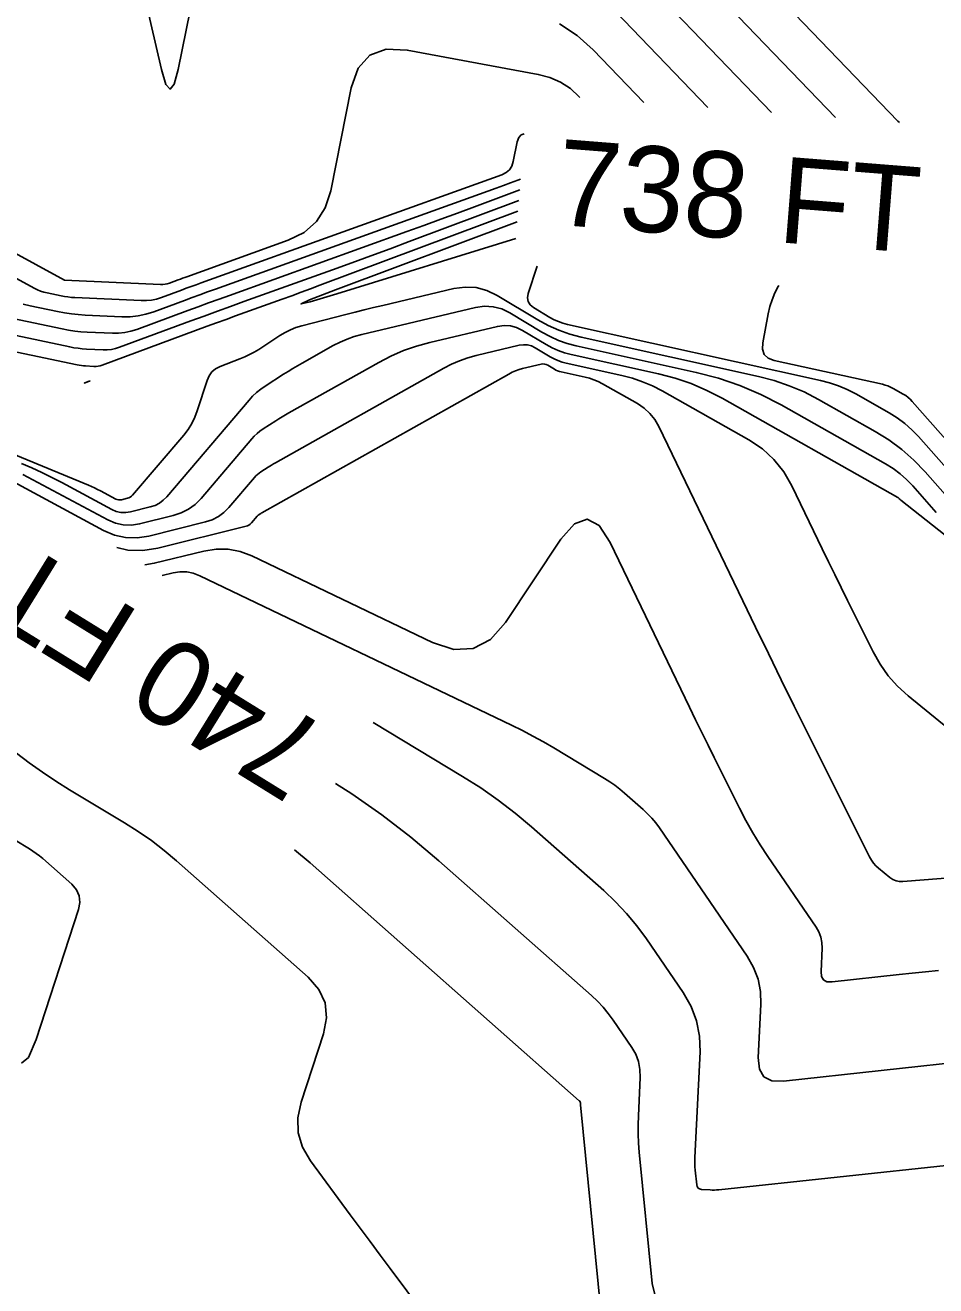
# Model space of a CAD drawing. Extents: x 1354696 to 1366163, y 660729 to 670380.
# Drawn here: x 1361169.7 to 1361233.4, y 664810.1 to 664898.2 of the extents above; entities that cross this region are included whole.
import ezdxf

# ---------------------------------------------------------------- set-up
doc = ezdxf.new("R2010")
doc.units = 0
doc.layers.add('R_Contour Annot', color=7, linetype='Continuous')
doc.layers.add('R_Contours', color=7, linetype='Continuous')

msp = doc.modelspace()

# ---------------------------------------------------------------- linework, layer by layer
at = {"layer": 'R_Contours'}
for points in [[(1361230.827, 664891.392), (1361230.814, 664891.4), (1361230.712, 664891.488), (1361207.938, 664915.166), (1361207.657, 664915.418), (1361207.348, 664915.618), (1361207.011, 664915.766), (1361206.647, 664915.862), (1361205.133, 664916.144), (1361204.754, 664916.21), (1361204.373, 664916.266), (1361203.991, 664916.313), (1361203.608, 664916.351), (1361192.611, 664917.287), (1361190.73, 664917.615), (1361189.007, 664918.265), (1361187.444, 664919.238), (1361186.04, 664920.532), (1361180.454, 664926.67), (1361179.143, 664927.771), (1361177.736, 664928.302), (1361176.233, 664928.261), (1361174.634, 664927.648), (1361166.891, 664923.427)], [(1361169.633, 664915.652), (1361195.317, 664913.464), (1361196.533, 664913.346), (1361197.746, 664913.197), (1361198.955, 664913.018), (1361200.159, 664912.809), (1361204.969, 664911.913), (1361206.127, 664911.607), (1361207.196, 664911.136), (1361208.177, 664910.501), (1361209.069, 664909.702), (1361226.339, 664891.747)], [(1361151.88, 664906.534), (1361170.71, 664912.233), (1361170.948, 664912.287), (1361171.186, 664912.303), (1361171.423, 664912.283), (1361171.66, 664912.225), (1361172.607, 664911.919), (1361172.845, 664911.849), (1361173.086, 664911.794), (1361173.329, 664911.752), (1361173.576, 664911.724), (1361187.025, 664910.578), (1361189.075, 664910.378), (1361191.119, 664910.127), (1361193.155, 664909.826), (1361195.185, 664909.473), (1361203.29, 664907.964), (1361205.242, 664907.448), (1361207.044, 664906.655), (1361208.697, 664905.585), (1361210.2, 664904.238), (1361221.876, 664892.1)], [(1361163.516, 664905.861), (1361172.724, 664908.648), (1361173.122, 664908.738), (1361173.519, 664908.765), (1361173.916, 664908.73), (1361174.313, 664908.634), (1361175.897, 664908.122), (1361176.295, 664908.006), (1361176.698, 664907.912), (1361177.106, 664907.842), (1361177.518, 664907.795), (1361182.556, 664907.366), (1361183.532, 664907.271), (1361184.505, 664907.152), (1361185.474, 664907.008), (1361186.44, 664906.84), (1361202.968, 664903.762), (1361205.06, 664903.209), (1361206.992, 664902.359), (1361208.764, 664901.212), (1361210.376, 664899.768), (1361217.412, 664892.452)], [(1361181.508, 664900.634), (1361180.407, 664895.112), (1361180.127, 664894.075), (1361179.836, 664893.727), (1361179.537, 664894.067), (1361179.227, 664895.095), (1361177.01, 664904.769)], [(1361212.949, 664892.805), (1361209.408, 664896.486), (1361208.289, 664897.489), (1361207.059, 664898.285)], [(1361208.485, 664893.158), (1361208.44, 664893.205), (1361207.814, 664893.765), (1361207.127, 664894.21), (1361206.377, 664894.54), (1361205.565, 664894.755), (1361196.409, 664896.46), (1361194.942, 664896.523), (1361193.801, 664896.102), (1361192.987, 664895.2), (1361192.499, 664893.815), (1361191.065, 664886.622), (1361190.687, 664885.444), (1361190.065, 664884.476), (1361189.2, 664883.719), (1361188.091, 664883.171), (1361181.009, 664880.624), (1361180.857, 664880.569), (1361180.705, 664880.514), (1361180.553, 664880.458), (1361180.401, 664880.403), (1361179.794, 664880.178), (1361179.641, 664880.13), (1361179.485, 664880.098), (1361179.327, 664880.082), (1361179.167, 664880.081), (1361172.461, 664880.386), (1361172.454, 664880.387), (1361172.453, 664880.388), (1361160.148, 664887.1)], [(1361161.836, 664884.468), (1361170.34, 664879.829), (1361170.559, 664879.72), (1361170.783, 664879.627), (1361171.015, 664879.551), (1361171.252, 664879.492), (1361172.214, 664879.29), (1361172.455, 664879.245), (1361172.697, 664879.209), (1361172.941, 664879.183), (1361173.186, 664879.167), (1361177.819, 664878.957), (1361178.184, 664878.958), (1361178.543, 664878.995), (1361178.896, 664879.068), (1361179.244, 664879.178), (1361180.623, 664879.687), (1361180.968, 664879.814), (1361181.313, 664879.94), (1361181.659, 664880.065), (1361182.005, 664880.19), (1361203.028, 664887.751), (1361203.326, 664887.898), (1361203.558, 664888.101), (1361203.725, 664888.36), (1361203.826, 664888.676), (1361204.1, 664890.052), (1361204.203, 664890.345), (1361204.376, 664890.536), (1361204.58, 664890.611)], [(1361168.845, 664877.704), (1361172.304, 664876.977), (1361172.735, 664876.896), (1361173.169, 664876.832), (1361173.605, 664876.785), (1361174.044, 664876.757), (1361175.802, 664876.677), (1361176.238, 664876.678), (1361176.668, 664876.723), (1361177.091, 664876.811), (1361177.507, 664876.941), (1361181.067, 664878.255), (1361181.799, 664878.524), (1361182.531, 664878.792), (1361183.263, 664879.058), (1361183.996, 664879.322), (1361196.389, 664883.779), (1361197.573, 664884.207), (1361198.755, 664884.638), (1361199.936, 664885.073), (1361201.115, 664885.512), (1361204.271, 664886.691)], [(1361204.33, 664887.437), (1361204.138, 664887.366), (1361203.639, 664887.182), (1361203.139, 664886.999), (1361202.639, 664886.819), (1361183, 664879.756), (1361182.461, 664879.562), (1361181.922, 664879.366), (1361181.383, 664879.169), (1361180.845, 664878.971), (1361178.693, 664878.177), (1361178.151, 664878.007), (1361177.6, 664877.892), (1361177.04, 664877.834), (1361176.472, 664877.832), (1361173.91, 664877.948), (1361173.421, 664877.98), (1361172.935, 664878.032), (1361172.451, 664878.104), (1361171.969, 664878.195), (1361170.048, 664878.598), (1361169.574, 664878.716)], [(1361204.212, 664885.946), (1361196.548, 664883.082), (1361195.211, 664882.585), (1361193.872, 664882.092), (1361192.533, 664881.603), (1361191.191, 664881.118), (1361184.992, 664878.889), (1361184.065, 664878.554), (1361183.139, 664878.218), (1361182.214, 664877.88), (1361181.29, 664877.54), (1361176.295, 664875.697), (1361176.018, 664875.609), (1361175.736, 664875.551), (1361175.449, 664875.521), (1361175.159, 664875.52), (1361173.986, 664875.573), (1361173.694, 664875.593), (1361173.403, 664875.624), (1361173.113, 664875.666), (1361172.826, 664875.721), (1361166.52, 664877.046)], [(1361164.113, 664876.404), (1361173.347, 664874.464), (1361173.492, 664874.437), (1361173.636, 664874.415), (1361173.782, 664874.4), (1361173.928, 664874.39), (1361174.515, 664874.364), (1361174.661, 664874.364), (1361174.804, 664874.379), (1361174.945, 664874.408), (1361175.084, 664874.452), (1361182.438, 664877.166), (1361183.092, 664877.407), (1361183.747, 664877.646), (1361184.402, 664877.884), (1361185.058, 664878.12), (1361187.682, 664879.064), (1361188.337, 664879.301), (1361188.992, 664879.54), (1361189.646, 664879.781), (1361190.299, 664880.024), (1361204.153, 664885.201)], [(1361204.002, 664883.286), (1361191.487, 664879.423), (1361189.624, 664878.867), (1361188.987, 664878.73), (1361189.575, 664879.01), (1361191.39, 664879.708), (1361204.094, 664884.456)], [(1361239.418, 664861.244), (1361232.153, 664869.457), (1361231.692, 664869.937), (1361231.196, 664870.374), (1361230.665, 664870.768), (1361230.098, 664871.119), (1361227.765, 664872.436), (1361227.172, 664872.742), (1361226.562, 664873.003), (1361225.934, 664873.216), (1361225.289, 664873.384), (1361207.616, 664877.292), (1361207.294, 664877.377), (1361206.983, 664877.487), (1361206.681, 664877.622), (1361206.39, 664877.782), (1361205.243, 664878.472), (1361205.006, 664878.662), (1361204.865, 664878.89), (1361204.822, 664879.153), (1361204.876, 664879.453), (1361205.489, 664881.357)], [(1361235.92, 664863.244), (1361232.601, 664866.996), (1361231.818, 664867.811), (1361230.976, 664868.552), (1361230.075, 664869.221), (1361229.114, 664869.816), (1361225.154, 664872.052), (1361224.149, 664872.571), (1361223.114, 664873.013), (1361222.049, 664873.376), (1361220.954, 664873.66), (1361208.57, 664876.399), (1361207.774, 664876.608), (1361207.003, 664876.88), (1361206.257, 664877.214), (1361205.535, 664877.61), (1361202.699, 664879.318), (1361201.978, 664879.668), (1361201.232, 664879.863), (1361200.463, 664879.904), (1361199.669, 664879.791), (1361194.714, 664878.621), (1361194.062, 664878.466), (1361193.412, 664878.307), (1361192.762, 664878.145), (1361192.113, 664877.979), (1361189.034, 664877.186), (1361188.634, 664877.066), (1361188.249, 664876.915), (1361187.877, 664876.733), (1361187.518, 664876.519), (1361186.029, 664875.55), (1361185.715, 664875.357), (1361185.391, 664875.181), (1361185.059, 664875.023), (1361184.718, 664874.882), (1361183.337, 664874.352), (1361183.02, 664874.192), (1361182.762, 664873.977), (1361182.562, 664873.707), (1361182.419, 664873.383), (1361181.735, 664871.261), (1361181.562, 664870.801), (1361181.347, 664870.366), (1361181.089, 664869.954), (1361180.789, 664869.565), (1361177.206, 664865.363), (1361177.132, 664865.288), (1361177.049, 664865.227), (1361176.958, 664865.18), (1361176.857, 664865.147), (1361176.439, 664865.044), (1361176.336, 664865.027), (1361176.235, 664865.03), (1361176.137, 664865.052), (1361176.041, 664865.094), (1361174.982, 664865.661), (1361174.773, 664865.77), (1361174.561, 664865.874), (1361174.347, 664865.972), (1361174.13, 664866.064), (1361149.744, 664876.128)], [(1361222.378, 664880.022), (1361222.337, 664879.949), (1361222.109, 664879.491), (1361221.917, 664879.019), (1361221.763, 664878.534), (1361221.647, 664878.035), (1361221.257, 664876.013), (1361221.235, 664875.556), (1361221.363, 664875.199), (1361221.64, 664874.94), (1361222.068, 664874.779), (1361229.625, 664873.108), (1361229.82, 664873.057), (1361230.011, 664872.992), (1361230.195, 664872.914), (1361230.375, 664872.821), (1361231.083, 664872.421), (1361231.254, 664872.315), (1361231.415, 664872.196), (1361231.566, 664872.063), (1361231.705, 664871.917), (1361243.389, 664858.709)], [(1361169.453, 664867.567), (1361170.168, 664867.261), (1361170.876, 664866.937), (1361171.575, 664866.596), (1361172.265, 664866.237), (1361175.757, 664864.364), (1361176.074, 664864.228), (1361176.399, 664864.155), (1361176.732, 664864.145), (1361177.073, 664864.199), (1361178.453, 664864.54), (1361178.783, 664864.649), (1361179.085, 664864.803), (1361179.359, 664865.004), (1361179.603, 664865.252), (1361185.353, 664871.995), (1361185.608, 664872.274), (1361185.882, 664872.532), (1361186.174, 664872.769), (1361186.484, 664872.985), (1361187.761, 664873.808), (1361188.082, 664874.011), (1361188.406, 664874.209), (1361188.732, 664874.403), (1361189.062, 664874.591), (1361191.233, 664875.812), (1361191.713, 664876.06), (1361192.206, 664876.272), (1361192.712, 664876.45), (1361193.233, 664876.592), (1361201.194, 664878.472), (1361201.821, 664878.561), (1361202.428, 664878.528), (1361203.016, 664878.374), (1361203.586, 664878.098), (1361205.825, 664876.75), (1361206.395, 664876.437), (1361206.984, 664876.174), (1361207.593, 664875.959), (1361208.221, 664875.793), (1361216.618, 664873.937), (1361218.163, 664873.535), (1361219.665, 664873.023), (1361221.126, 664872.4), (1361222.544, 664871.667), (1361229.847, 664867.545), (1361230.369, 664867.221), (1361230.859, 664866.858), (1361231.317, 664866.454), (1361231.743, 664866.011), (1361233.382, 664864.158)], [(1361246.854, 664852.442), (1361230.912, 664865.009), (1361230.894, 664865.024), (1361230.877, 664865.039), (1361230.86, 664865.055), (1361230.845, 664865.072), (1361230.783, 664865.141), (1361230.768, 664865.158), (1361230.75, 664865.173), (1361230.732, 664865.187), (1361230.713, 664865.199), (1361218.42, 664872.137), (1361217.357, 664872.686), (1361216.263, 664873.153), (1361215.137, 664873.537), (1361213.979, 664873.838), (1361207.872, 664875.188), (1361207.411, 664875.309), (1361206.965, 664875.467), (1361206.533, 664875.66), (1361206.115, 664875.889), (1361204.473, 664876.878), (1361204.055, 664877.08), (1361203.624, 664877.194), (1361203.178, 664877.217), (1361202.719, 664877.152), (1361197.993, 664876.036), (1361197.063, 664875.782), (1361196.157, 664875.465), (1361195.275, 664875.085), (1361194.418, 664874.641), (1361188.128, 664871.106), (1361187.898, 664870.974), (1361187.671, 664870.839), (1361187.445, 664870.701), (1361187.222, 664870.56), (1361186.332, 664869.987), (1361186.116, 664869.836), (1361185.913, 664869.671), (1361185.722, 664869.491), (1361185.544, 664869.297), (1361182, 664865.141), (1361181.585, 664864.721), (1361181.121, 664864.38), (1361180.609, 664864.117), (1361180.048, 664863.933), (1361177.707, 664863.354), (1361177.129, 664863.263), (1361176.564, 664863.279), (1361176.012, 664863.403), (1361175.474, 664863.634), (1361169.549, 664866.812)], [(1361167.443, 664867.06), (1361175.191, 664862.905), (1361175.95, 664862.578), (1361176.728, 664862.404), (1361177.525, 664862.381), (1361178.341, 664862.509), (1361182.308, 664863.491), (1361182.781, 664863.646), (1361183.212, 664863.867), (1361183.603, 664864.155), (1361183.953, 664864.508), (1361185.736, 664866.599), (1361185.836, 664866.709), (1361185.944, 664866.81), (1361186.059, 664866.903), (1361186.181, 664866.988), (1361186.683, 664867.312), (1361186.809, 664867.392), (1361186.936, 664867.47), (1361187.065, 664867.546), (1361187.194, 664867.62), (1361198.962, 664874.235), (1361199.507, 664874.517), (1361200.068, 664874.759), (1361200.645, 664874.961), (1361201.237, 664875.122), (1361204.244, 664875.832), (1361204.536, 664875.874), (1361204.82, 664875.859), (1361205.094, 664875.787), (1361205.36, 664875.658), (1361206.405, 664875.029), (1361206.671, 664874.883), (1361206.946, 664874.76), (1361207.23, 664874.66), (1361207.523, 664874.583), (1361211.409, 664873.723), (1361212.146, 664873.532), (1361212.862, 664873.288), (1361213.559, 664872.991), (1361214.235, 664872.641), (1361220.294, 664869.221), (1361221.232, 664868.598), (1361222.044, 664867.856), (1361222.731, 664866.997), (1361223.292, 664866.021), (1361225.411, 664861.618), (1361225.848, 664860.714), (1361226.289, 664859.811), (1361226.732, 664858.91), (1361227.179, 664858.011), (1361228.972, 664854.416), (1361229.462, 664853.55), (1361230.033, 664852.75), (1361230.687, 664852.016), (1361231.424, 664851.347), (1361237.34, 664846.512)], [(1361241.152, 664839.169), (1361231.059, 664838.366), (1361230.81, 664838.369), (1361230.575, 664838.417), (1361230.355, 664838.511), (1361230.149, 664838.65), (1361229.353, 664839.301), (1361229.165, 664839.472), (1361228.998, 664839.659), (1361228.852, 664839.864), (1361228.726, 664840.085), (1361223.467, 664850.627), (1361222.556, 664852.462), (1361221.651, 664854.301), (1361220.753, 664856.142), (1361219.861, 664857.987), (1361214.005, 664870.155), (1361213.723, 664870.646), (1361213.377, 664871.078), (1361212.969, 664871.45), (1361212.498, 664871.764), (1361210.05, 664873.145), (1361209.76, 664873.295), (1361209.462, 664873.422), (1361209.155, 664873.527), (1361208.839, 664873.609), (1361207.174, 664873.977), (1361207.048, 664874.01), (1361206.926, 664874.053), (1361206.809, 664874.106), (1361206.695, 664874.168), (1361206.247, 664874.438), (1361206.133, 664874.493), (1361206.016, 664874.524), (1361205.894, 664874.531), (1361205.769, 664874.513), (1361204.48, 664874.209), (1361204.227, 664874.139), (1361203.979, 664874.053), (1361203.739, 664873.949), (1361203.505, 664873.828), (1361186.26, 664864.134), (1361186.231, 664864.117), (1361186.202, 664864.1), (1361186.173, 664864.082), (1361186.144, 664864.064), (1361186.029, 664863.99), (1361186.001, 664863.971), (1361185.975, 664863.95), (1361185.95, 664863.926), (1361185.928, 664863.901), (1361185.52, 664863.424), (1361185.44, 664863.343), (1361185.351, 664863.278), (1361185.253, 664863.227), (1361185.145, 664863.192), (1361178.975, 664861.665), (1361177.921, 664861.499), (1361176.892, 664861.528), (1361176.114, 664861.703)], [(1361178.065, 664860.498), (1361178.73, 664860.602), (1361182.197, 664861.46), (1361183.056, 664861.6), (1361183.9, 664861.589), (1361184.728, 664861.429), (1361185.541, 664861.118), (1361198.175, 664855.063), (1361199.677, 664854.584), (1361201.027, 664854.657), (1361202.225, 664855.284), (1361203.271, 664856.464), (1361207.15, 664862.291), (1361208.093, 664863.369), (1361208.984, 664863.688), (1361209.822, 664863.249), (1361210.607, 664862.051), (1361216.141, 664850.552), (1361216.569, 664849.667), (1361217, 664848.784), (1361217.434, 664847.902), (1361217.871, 664847.022), (1361219.626, 664843.503), (1361220.08, 664842.632), (1361220.562, 664841.779), (1361221.074, 664840.942), (1361221.614, 664840.122), (1361224.992, 664835.187), (1361225.19, 664834.843), (1361225.326, 664834.481), (1361225.4, 664834.101), (1361225.412, 664833.704), (1361225.333, 664832.08), (1361225.366, 664831.731), (1361225.506, 664831.494), (1361225.751, 664831.369), (1361226.102, 664831.357), (1361230.794, 664831.874), (1361231.711, 664831.971), (1361232.629, 664832.061), (1361233.547, 664832.145)], [(1361179.292, 664859.74), (1361180.048, 664859.927), (1361180.527, 664860.005), (1361180.997, 664859.999), (1361181.459, 664859.909), (1361181.912, 664859.736), (1361203.711, 664849.289), (1361204.46, 664848.92), (1361205.199, 664848.533), (1361205.929, 664848.129), (1361206.65, 664847.707), (1361210.2, 664845.573), (1361210.567, 664845.341), (1361210.922, 664845.094), (1361211.265, 664844.83), (1361211.596, 664844.551), (1361212.899, 664843.401), (1361213.215, 664843.104), (1361213.51, 664842.79), (1361213.786, 664842.458), (1361214.041, 664842.109), (1361220.171, 664833.152), (1361220.623, 664832.367), (1361220.934, 664831.541), (1361221.102, 664830.676), (1361221.128, 664829.77), (1361220.949, 664826.066), (1361221.025, 664825.268), (1361221.342, 664824.727), (1361221.901, 664824.443), (1361222.702, 664824.416), (1361236.358, 664825.919)], [(1361234.736, 664818.603), (1361218.182, 664816.829), (1361218.031, 664816.816), (1361217.88, 664816.81), (1361217.729, 664816.81), (1361217.578, 664816.818), (1361216.974, 664816.86), (1361216.84, 664816.888), (1361216.74, 664816.951), (1361216.674, 664817.049), (1361216.642, 664817.182), (1361216.54, 664818.204), (1361216.522, 664818.424), (1361216.513, 664818.645), (1361216.511, 664818.866), (1361216.518, 664819.087), (1361216.875, 664826.458), (1361216.843, 664827.568), (1361216.637, 664828.629), (1361216.256, 664829.64), (1361215.701, 664830.603), (1361213.135, 664834.353), (1361212.467, 664835.268), (1361211.746, 664836.136), (1361210.973, 664836.958), (1361210.148, 664837.733), (1361205.104, 664842.185), (1361203.96, 664843.151), (1361202.775, 664844.061), (1361201.549, 664844.916), (1361200.284, 664845.716), (1361194.036, 664849.471)], [(1361169.096, 664847.332), (1361169.992, 664846.653), (1361170.908, 664846.002), (1361171.843, 664845.379), (1361172.798, 664844.785), (1361176.657, 664842.466), (1361177.606, 664841.866), (1361178.526, 664841.224), (1361179.415, 664840.541), (1361180.274, 664839.817), (1361189.483, 664831.686), (1361190.24, 664830.83), (1361190.672, 664829.885), (1361190.779, 664828.851), (1361190.56, 664827.729), (1361188.997, 664822.951), (1361188.766, 664821.862), (1361188.799, 664820.815), (1361189.096, 664819.811), (1361189.657, 664818.849), (1361192.429, 664815.087), (1361193.123, 664814.147), (1361193.818, 664813.208), (1361194.514, 664812.27), (1361195.212, 664811.333), (1361206.858, 664795.721)], [(1361213.771, 664809.318), (1361213.542, 664810.271), (1361212.631, 664819.455), (1361212.579, 664820.091), (1361212.551, 664820.728), (1361212.547, 664821.365), (1361212.566, 664822.003), (1361212.696, 664824.684), (1361212.68, 664825.246), (1361212.575, 664825.783), (1361212.383, 664826.295), (1361212.102, 664826.783), (1361210.802, 664828.682), (1361210.464, 664829.145), (1361210.099, 664829.585), (1361209.707, 664830.001), (1361209.289, 664830.394), (1361198.612, 664839.82), (1361196.654, 664841.471), (1361194.628, 664843.028), (1361192.532, 664844.491), (1361191.401, 664845.206)], [(1361169.004, 664841.249), (1361169.999, 664840.651), (1361170.244, 664840.496), (1361170.481, 664840.331), (1361170.71, 664840.155), (1361170.931, 664839.968), (1361172.959, 664838.178), (1361173.297, 664837.796), (1361173.49, 664837.374), (1361173.537, 664836.913), (1361173.44, 664836.412), (1361170.473, 664827.342), (1361169.944, 664826.084), (1361169.459, 664825.681)], [(1361210.461, 664803.175), (1361208.516, 664822.777), (1361208.514, 664822.793), (1361208.514, 664822.809), (1361208.514, 664822.825), (1361208.514, 664822.842), (1361208.517, 664822.91), (1361208.517, 664822.924), (1361208.514, 664822.938), (1361208.509, 664822.951), (1361208.502, 664822.963), (1361208.469, 664823.011), (1361208.461, 664823.023), (1361208.451, 664823.034), (1361208.442, 664823.045), (1361208.431, 664823.055), (1361189.616, 664839.666), (1361188.539, 664840.574)]]:
    msp.add_lwpolyline(points, dxfattribs=at)
msp.add_lwpolyline([(1361173.89, 664873.208), (1361173.888, 664873.206), (1361173.886, 664873.203), (1361173.885, 664873.2), (1361173.88, 664873.186), (1361173.879, 664873.183), (1361173.877, 664873.182), (1361173.875, 664873.183), (1361173.873, 664873.185), (1361173.853, 664873.208), (1361173.852, 664873.209), (1361173.852, 664873.21), (1361173.853, 664873.211), (1361173.855, 664873.21), (1361173.87, 664873.207), (1361173.873, 664873.207), (1361174.192, 664873.325), (1361174.23, 664873.339), (1361174.243, 664873.344), (1361174.23, 664873.338), (1361174.192, 664873.324), (1361173.893, 664873.209)], close=True, dxfattribs=at)

# ---------------------------------------------------------------- texts
at = {"layer": 'R_Contour Annot'}
for s, rotation, p in [('738 FT', 355.48152, (1361206.662, 664884.274)), ('740 FT', 148.29199, (1361191.189, 664848.863))]:
    msp.add_text(s, height=6, rotation=rotation, dxfattribs=at).set_placement(p)

doc.saveas('drawing.dxf')
